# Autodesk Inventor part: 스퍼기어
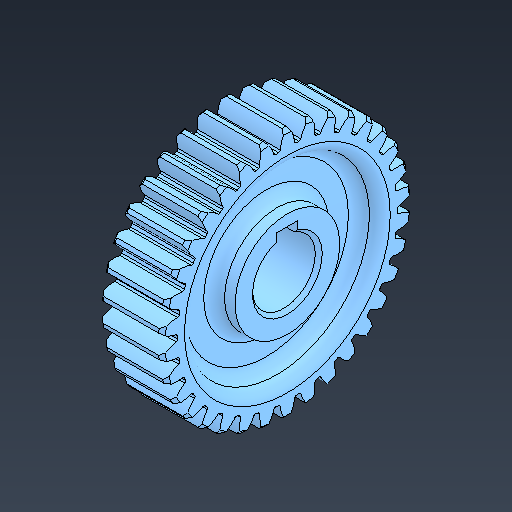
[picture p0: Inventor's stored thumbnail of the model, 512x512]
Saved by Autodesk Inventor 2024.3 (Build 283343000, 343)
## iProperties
Created: 2025-07
Part Number: 스퍼기어
Material: 강철, 합금
Document SubType Name: Modeling
Designer: user
Density: 7.73 g/cm^3
Appearance: 기본값
Author: jhkim
Sending System: Autodesk Inventor 2026
Preprocessor: ST-DEVELOPER v20.1
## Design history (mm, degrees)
feature "솔리드1"
node "솔리드2"
